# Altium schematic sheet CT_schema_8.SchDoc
size 255 x 245 mm
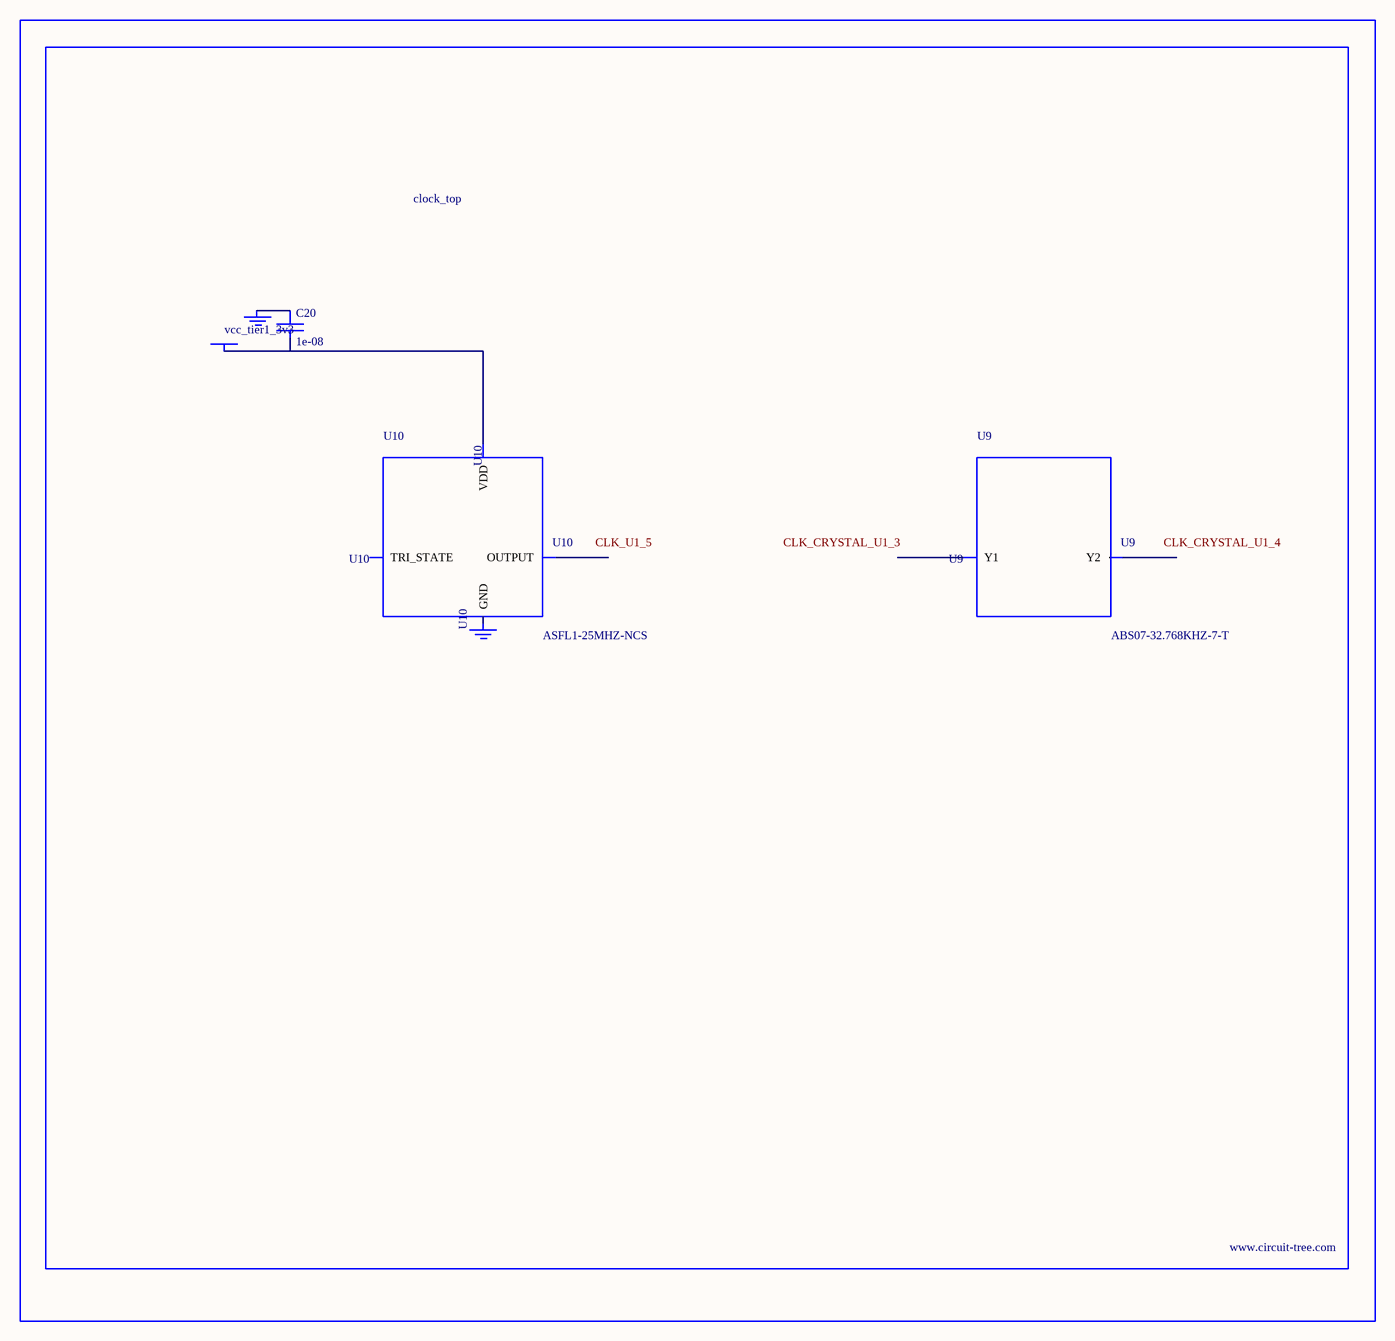
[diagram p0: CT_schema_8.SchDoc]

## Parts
BORDER7  (no value)
C20  1e-08  [C0402]
GND_INSTANCE_7_0  (no value)
GND_INSTANCE_7_1  (no value)
POWER_INSTANCE_7_0  vcc_tier1_3v3
U9  ABS07-32.768KHZ-7-T  [ABS07-32.768KHZ-7-T]
U10  ASFL1-25MHZ-NCS  [ASFL1]

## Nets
NetC20_1: C20.1 GND_INSTANCE_7_0.0(GND)
NetC20_2: C20.2 POWER_INSTANCE_7_0.0(PWR) U10.4(VDD)

Not connected (* = marked no-connect by the designer): GND_INSTANCE_7_1 0(GND); U9 1(Y1) 2(Y2); U10 1(TRI_STATE) 2(GND) 3(OUTPUT)

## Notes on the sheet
- Labels drawn without touching a wire or pin: CLK_CRYSTAL_U1_3, CLK_CRYSTAL_U1_4, CLK_U1_5

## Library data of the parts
BORDER7 = BORDER_PAGE7
C20 = C0402C103K3RAC
GND_INSTANCE_7_0 GND_INSTANCE_7_1 = GND
POWER_INSTANCE_7_0 = PWR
